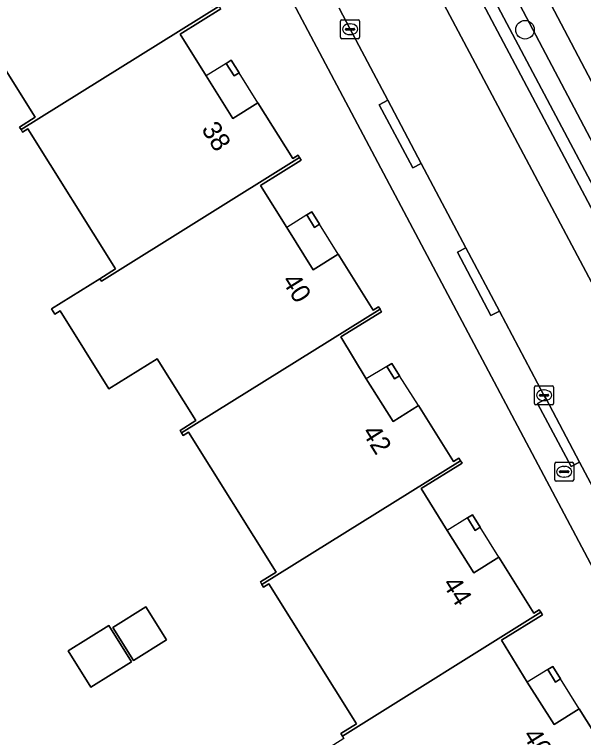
# Model space of a CAD drawing. Extents: x 158835 to 160077, y 386387 to 387778.
# Drawn here: x 159225.67 to 159255.61, y 387026.31 to 387064.34 of the extents above; entities that cross this region are included whole.
import ezdxf

# ---------------------------------------------------------------- set-up
doc = ezdxf.new("R2010")
doc.units = 0
for name, color, linetype in [('IMGEO_Berm_groen', 7, 'Continuous'), ('IMGEO_Boom', 7, 'Continuous'), ('IMGEO_Brandkraan', 7, 'Continuous'), ('IMGEO_Erf', 7, 'Continuous'), ('IMGEO_Kolk', 7, 'Continuous'), ('IMGEO_Oever', 7, 'Continuous'), ('IMGEO_Pand', 7, 'Continuous'), ('IMGEO_Pand_nummerreeks', 7, 'Continuous'), ('IMGEO_Pand_overbouw', 7, 'Continuous'), ('IMGEO_Parkeervlak_open', 7, 'Continuous'), ('IMGEO_Rijbaan_lokaal_open', 7, 'Continuous'), ('IMGEO_Voetpad_open', 7, 'Continuous'), ('IMGEO_Waterloop', 7, 'Continuous')]:
    doc.layers.add(name, color=color, linetype=linetype)

msp = doc.modelspace()

# ---------------------------------------------------------------- linework, layer by layer
at = {"layer": 'IMGEO_Berm_groen'}
for points in [[(159232.161, 387115.069), (159226.137, 387111.804), (159270.438, 387028.309), (159271.271, 387028.784), (159272.996, 387034.162)], [(159268.044, 387034.942), (159228.447, 387109.997)]]:
    msp.add_lwpolyline(points, dxfattribs=at)
at = {"layer": 'IMGEO_Boom'}
msp.add_circle((159252.526, 387063.537), 0.489, dxfattribs=at)
at = {"layer": 'IMGEO_Brandkraan'}
for p, q in [((159254.089, 387039.861), (159254.089, 387040.713)), ((159254.164, 387040.787), (159255.016, 387040.787)), ((159255.09, 387040.713), (159255.09, 387039.861)), ((159254.348, 387040.281), (159254.348, 387040.293)), ((159254.786, 387040.244), (159254.388, 387040.244)), ((159254.391, 387040.33), (159254.789, 387040.33)), ((159254.577, 387040.567), (159254.602, 387040.567)), ((159254.832, 387040.293), (159254.832, 387040.281)), ((159254.6, 387040.007), (159254.575, 387040.007)), ((159255.016, 387039.787), (159254.164, 387039.787))]:
    msp.add_line(p, q, dxfattribs=at)
for points in [[(159254.089, 387039.861), (159254.089, 387040.713)], [(159254.164, 387040.787), (159255.016, 387040.787)], [(159255.09, 387040.713), (159255.09, 387039.861)], [(159255.016, 387039.787), (159254.164, 387039.787)]]:
    msp.add_lwpolyline(points, dxfattribs=at)
for centre, radius, start, end in [((159254.166, 387040.711), 0.0765, 91.552, 178.448), ((159254.166, 387040.711), 0.0765, 91.552, 178.448), ((159255.014, 387040.711), 0.0765, 1.552, 88.448), ((159255.014, 387040.711), 0.0765, 1.552, 88.448), ((159254.388, 387040.29), 0.0403, 85.8775, 175.7526), ((159254.385, 387040.28), 0.0366, 178.938, 274.7102), ((159254.789, 387040.287), 0.043, 264.8664, 352.4533), ((159254.793, 387040.292), 0.0386, 1.7309, 96.639), ((159254.166, 387039.863), 0.0765, 181.552, 268.448), ((159254.166, 387039.863), 0.0765, 181.552, 268.448), ((159255.014, 387039.863), 0.0765, 271.552, 358.448), ((159255.014, 387039.863), 0.0765, 271.552, 358.448)]:
    msp.add_arc(centre, radius, start, end, dxfattribs=at)
for centre, major_axis, ratio, start_param, end_param in [((159254.576, 387040.287), (-0.387, 0.002), 0.722429, 4.712389, 7.853982), ((159254.601, 387040.287), (-0.39, 0.002), 0.717154, 1.570796, 4.712389)]:
    msp.add_ellipse(centre, major_axis=major_axis, ratio=ratio, start_param=start_param, end_param=end_param, dxfattribs=at)
at = {"layer": 'IMGEO_Erf'}
for points in [[(159261.184, 387025.643), (159192.812, 387154.528)], [(159243.003, 387026.25), (159242.922, 387026.379), (159242.837, 387026.515), (159243.66, 387027.029), (159239.055, 387034.398), (159238.776, 387034.223), (159238.691, 387034.359), (159238.606, 387034.495), (159239.429, 387035.009), (159234.83, 387042.369), (159234.55, 387042.195), (159234.465, 387042.33), (159234.38, 387042.466), (159235.211, 387042.985), (159233.182, 387046.233), (159230.638, 387044.643), (159228.068, 387048.756), (159227.788, 387048.581), (159227.619, 387048.853), (159230.162, 387050.442), (159230.985, 387050.956), (159226.381, 387058.325), (159226.101, 387058.15), (159226.016, 387058.286), (159225.932, 387058.422), (159226.754, 387058.936), (159222.155, 387066.296)], [(159236.531, 387064.64), (159234.39, 387063.311), (159235.756, 387061.11), (159237.152, 387058.876), (159238.473, 387059.701), (159240.308, 387056.773), (159240.588, 387056.948), (159240.673, 387056.813), (159240.758, 387056.677), (159238.613, 387055.337), (159239.99, 387053.137), (159241.386, 387050.903), (159242.706, 387051.728), (159244.538, 387048.796), (159244.818, 387048.97), (159244.903, 387048.834), (159244.987, 387048.699), (159242.834, 387047.389), (159244.18, 387045.177), (159245.598, 387042.94), (159246.918, 387043.765), (159248.767, 387040.829), (159249.047, 387041.006), (159249.133, 387040.87), (159249.218, 387040.734), (159247.073, 387039.403), (159248.44, 387037.198), (159249.837, 387034.964), (159251.158, 387035.789), (159252.992, 387032.856), (159253.272, 387033.032), (159253.357, 387032.896), (159253.442, 387032.76), (159251.286, 387031.433), (159252.65, 387029.217), (159254.063, 387026.986), (159255.383, 387027.811), (159257.214, 387024.885)]]:
    msp.add_lwpolyline(points, dxfattribs=at)
for points in [[(159237.076, 387061.93), (159237.485, 387061.278), (159237.222, 387061.113), (159236.813, 387061.766)], [(159241.313, 387053.959), (159241.721, 387053.306), (159241.458, 387053.142), (159241.05, 387053.795)], [(159245.516, 387045.99), (159245.927, 387045.338), (159245.664, 387045.173), (159245.251, 387045.829)], [(159249.763, 387038.019), (159250.171, 387037.366), (159249.908, 387037.202), (159249.5, 387037.856)], [(159233.67, 387031.446), (159231.931, 387030.359), (159230.843, 387032.098), (159232.582, 387033.185)], [(159231.831, 387030.293), (159229.688, 387028.952), (159228.493, 387030.863), (159230.637, 387032.203)], [(159253.988, 387030.041), (159254.396, 387029.388), (159254.134, 387029.224), (159253.724, 387029.878)]]:
    msp.add_lwpolyline(points, close=True, dxfattribs=at)
at = {"layer": 'IMGEO_Kolk'}
for p, q in [((159242.824, 387063.139), (159242.824, 387063.991)), ((159242.899, 387064.065), (159243.751, 387064.065)), ((159243.312, 387063.845), (159243.337, 387063.845)), ((159243.825, 387063.991), (159243.825, 387063.139)), ((159243.083, 387063.559), (159243.083, 387063.571)), ((159243.521, 387063.522), (159243.123, 387063.522)), ((159243.126, 387063.608), (159243.524, 387063.608)), ((159243.567, 387063.571), (159243.567, 387063.559)), ((159243.751, 387063.065), (159242.899, 387063.065)), ((159243.335, 387063.285), (159243.31, 387063.285)), ((159253.104, 387044.812), (159253.956, 387044.812)), ((159253.029, 387043.886), (159253.029, 387044.738)), ((159253.517, 387044.592), (159253.542, 387044.592)), ((159254.03, 387044.738), (159254.03, 387043.886)), ((159253.288, 387044.306), (159253.288, 387044.318)), ((159253.726, 387044.269), (159253.328, 387044.269)), ((159253.331, 387044.355), (159253.729, 387044.355)), ((159253.772, 387044.318), (159253.772, 387044.306)), ((159253.956, 387043.812), (159253.104, 387043.812)), ((159253.54, 387044.032), (159253.515, 387044.032))]:
    msp.add_line(p, q, dxfattribs=at)
for points in [[(159242.824, 387063.139), (159242.824, 387063.991)], [(159242.899, 387064.065), (159243.751, 387064.065)], [(159243.825, 387063.991), (159243.825, 387063.139)], [(159243.751, 387063.065), (159242.899, 387063.065)], [(159253.104, 387044.812), (159253.956, 387044.812)], [(159253.029, 387043.886), (159253.029, 387044.738)], [(159254.03, 387044.738), (159254.03, 387043.886)], [(159253.956, 387043.812), (159253.104, 387043.812)]]:
    msp.add_lwpolyline(points, dxfattribs=at)
for centre, radius, start, end in [((159242.901, 387063.989), 0.0765, 91.552, 178.448), ((159242.901, 387063.989), 0.0765, 91.552, 178.448), ((159243.749, 387063.989), 0.0765, 1.552, 88.448), ((159243.749, 387063.989), 0.0765, 1.552, 88.448), ((159243.123, 387063.568), 0.0403, 85.8775, 175.7526), ((159243.12, 387063.558), 0.0366, 178.938, 274.7102), ((159243.524, 387063.565), 0.043, 264.8664, 352.4533), ((159243.528, 387063.57), 0.0386, 1.7309, 96.639), ((159242.901, 387063.141), 0.0765, 181.552, 268.448), ((159242.901, 387063.141), 0.0765, 181.552, 268.448), ((159243.749, 387063.141), 0.0765, 271.552, 358.448), ((159243.749, 387063.141), 0.0765, 271.552, 358.448), ((159253.106, 387044.736), 0.0765, 91.552, 178.448), ((159253.106, 387044.736), 0.0765, 91.552, 178.448), ((159253.954, 387044.736), 0.0765, 1.552, 88.448), ((159253.954, 387044.736), 0.0765, 1.552, 88.448), ((159253.328, 387044.315), 0.0403, 85.8775, 175.7526), ((159253.325, 387044.305), 0.0366, 178.938, 274.7102), ((159253.729, 387044.312), 0.043, 264.8664, 352.4533), ((159253.733, 387044.317), 0.0386, 1.7309, 96.639), ((159253.106, 387043.888), 0.0765, 181.552, 268.448), ((159253.106, 387043.888), 0.0765, 181.552, 268.448), ((159253.954, 387043.888), 0.0765, 271.552, 358.448), ((159253.954, 387043.888), 0.0765, 271.552, 358.448)]:
    msp.add_arc(centre, radius, start, end, dxfattribs=at)
for centre, major_axis, ratio, start_param, end_param in [((159243.311, 387063.565), (-0.387, 0.002), 0.722429, 4.712389, 7.853982), ((159243.336, 387063.565), (-0.39, 0.002), 0.717154, 1.570796, 4.712389), ((159253.516, 387044.312), (-0.387, 0.002), 0.722429, 4.712389, 7.853982), ((159253.541, 387044.312), (-0.39, 0.002), 0.717154, 1.570796, 4.712389)]:
    msp.add_ellipse(centre, major_axis=major_axis, ratio=ratio, start_param=start_param, end_param=end_param, dxfattribs=at)
at = {"layer": 'IMGEO_Oever'}
for points in [[(159228.447, 387109.997), (159268.044, 387034.942)], [(159232.07, 387109.817), (159271.865, 387035.443), (159269.914, 387034.437), (159263.508, 387046.573), (159249.976, 387072.343), (159230.366, 387108.873)]]:
    msp.add_lwpolyline(points, dxfattribs=at)
at = {"layer": 'IMGEO_Pand'}
for points in [[(159234.24, 387067.673), (159232.92, 387066.848), (159231.509, 387069.082), (159230.151, 387071.292), (159232.302, 387072.614), (159232.217, 387072.75), (159221.79, 387066.257), (159221.875, 387066.121), (159222.155, 387066.296), (159226.754, 387058.936), (159225.932, 387058.422), (159226.016, 387058.286), (159236.446, 387064.776), (159236.361, 387064.912), (159236.08, 387064.736)], [(159238.473, 387059.701), (159237.152, 387058.876), (159235.756, 387061.11), (159234.39, 387063.311), (159236.531, 387064.64), (159236.446, 387064.776), (159226.016, 387058.286), (159226.101, 387058.15), (159226.381, 387058.325), (159230.985, 387050.956), (159230.162, 387050.442), (159230.247, 387050.306), (159240.673, 387056.813), (159240.588, 387056.948), (159240.308, 387056.773)], [(159237.076, 387061.93), (159236.813, 387061.766), (159237.222, 387061.113), (159237.485, 387061.278)], [(159242.706, 387051.728), (159241.386, 387050.903), (159239.99, 387053.137), (159238.613, 387055.337), (159240.758, 387056.677), (159240.673, 387056.813), (159230.247, 387050.306), (159230.162, 387050.442), (159227.619, 387048.853), (159227.788, 387048.581), (159228.068, 387048.756), (159230.638, 387044.643), (159233.182, 387046.233), (159235.211, 387042.985), (159234.38, 387042.466), (159234.465, 387042.33), (159244.903, 387048.834), (159244.818, 387048.97), (159244.538, 387048.796)], [(159241.313, 387053.959), (159241.05, 387053.795), (159241.458, 387053.142), (159241.721, 387053.306)], [(159246.918, 387043.765), (159245.598, 387042.94), (159244.18, 387045.177), (159242.834, 387047.389), (159244.987, 387048.699), (159244.903, 387048.834), (159234.465, 387042.33), (159234.55, 387042.195), (159234.83, 387042.369), (159239.429, 387035.009), (159238.606, 387034.495), (159238.691, 387034.359), (159249.133, 387040.87), (159249.047, 387041.006), (159248.767, 387040.829)], [(159245.516, 387045.99), (159245.251, 387045.829), (159245.664, 387045.173), (159245.927, 387045.338)], [(159251.158, 387035.789), (159249.837, 387034.964), (159248.44, 387037.198), (159247.073, 387039.403), (159249.218, 387040.734), (159249.133, 387040.87), (159238.691, 387034.359), (159238.776, 387034.223), (159239.055, 387034.398), (159243.66, 387027.029), (159242.837, 387026.515), (159242.922, 387026.379), (159253.357, 387032.896), (159253.272, 387033.032), (159252.992, 387032.856)], [(159249.763, 387038.019), (159249.5, 387037.856), (159249.908, 387037.202), (159250.171, 387037.366)], [(159230.843, 387032.098), (159231.931, 387030.359), (159233.67, 387031.446), (159232.582, 387033.185)], [(159257.664, 387024.789), (159257.494, 387025.06), (159257.214, 387024.885), (159255.383, 387027.811), (159254.063, 387026.986), (159252.65, 387029.217), (159251.286, 387031.433), (159253.442, 387032.76), (159253.357, 387032.896), (159242.922, 387026.379), (159243.003, 387026.25), (159240.22, 387024.511), (159244.789, 387017.2), (159247.571, 387018.938), (159249.1, 387016.492), (159253.864, 387019.466), (159253.695, 387019.738), (159253.363, 387019.532), (159252.205, 387021.394)], [(159228.493, 387030.863), (159229.688, 387028.952), (159231.831, 387030.293), (159230.637, 387032.203)], [(159253.988, 387030.041), (159253.724, 387029.878), (159254.134, 387029.224), (159254.396, 387029.388)]]:
    msp.add_lwpolyline(points, close=True, dxfattribs=at)
at = {"layer": 'IMGEO_Pand_overbouw'}
for points in [[(159237.485, 387061.278), (159237.076, 387061.93), (159236.813, 387061.766), (159235.756, 387061.11), (159237.152, 387058.876), (159238.473, 387059.701)], [(159241.721, 387053.306), (159241.313, 387053.959), (159241.05, 387053.795), (159239.99, 387053.137), (159241.386, 387050.903), (159242.706, 387051.728)], [(159245.927, 387045.338), (159245.516, 387045.99), (159245.251, 387045.829), (159244.18, 387045.177), (159245.598, 387042.94), (159246.918, 387043.765)], [(159250.171, 387037.366), (159249.763, 387038.019), (159249.5, 387037.856), (159248.44, 387037.198), (159249.837, 387034.964), (159251.158, 387035.789)], [(159254.396, 387029.388), (159253.988, 387030.041), (159253.724, 387029.878), (159252.65, 387029.217), (159254.063, 387026.986), (159255.383, 387027.811)]]:
    msp.add_lwpolyline(points, close=True, dxfattribs=at)
at = {"layer": 'IMGEO_Parkeervlak_open'}
msp.add_lwpolyline([(159248.115, 387065.172), (159257.979, 387046.591), (159267.363, 387028.878), (159268.082, 387027.672), (159268.061, 387027.769), (159268.036, 387027.936), (159268.027, 387028.103), (159268.033, 387028.272), (159268.053, 387028.439), (159268.089, 387028.603), (159268.468, 387030.087), (159268.49, 387030.166), (159268.504, 387030.247), (159268.512, 387030.329), (159268.512, 387030.411), (159268.504, 387030.493), (159268.49, 387030.574), (159268.468, 387030.653), (159268.439, 387030.73), (159268.404, 387030.804), (159268.384, 387030.839), (159217.085, 387127.542)], dxfattribs=at)
at = {"layer": 'IMGEO_Rijbaan_lokaal_open'}
msp.add_lwpolyline([(159242.753, 387064.674), (159243.322, 387063.566), (159245.304, 387059.827), (159247.064, 387056.499), (159249.413, 387052.073), (159251.18, 387048.74), (159253.527, 387044.313), (159253.634, 387044.117), (159255.396, 387040.792), (159257.738, 387036.381), (159259.501, 387033.04), (159262.771, 387026.855), (159263.643, 387025.149), (159268.082, 387027.672), (159267.363, 387028.878), (159257.979, 387046.591), (159248.115, 387065.172)], dxfattribs=at)
at = {"layer": 'IMGEO_Voetpad_open'}
for points in [[(159192.812, 387154.528), (159261.184, 387025.643)], [(159217.085, 387127.542), (159268.384, 387030.839), (159268.404, 387030.804), (159268.439, 387030.73), (159268.468, 387030.653), (159268.49, 387030.574), (159268.504, 387030.493), (159268.512, 387030.411), (159268.512, 387030.329), (159268.504, 387030.247), (159268.49, 387030.166), (159268.468, 387030.087), (159268.089, 387028.603), (159268.053, 387028.439), (159268.033, 387028.272), (159268.027, 387028.103), (159268.036, 387027.936), (159268.061, 387027.769), (159268.082, 387027.672), (159268.126, 387027.544), (159268.184, 387027.373), (159268.337, 387027.091), (159270.438, 387028.309), (159226.137, 387111.804)], [(159263.643, 387025.149), (159262.771, 387026.855), (159259.501, 387033.04), (159259.059, 387032.807), (159257.296, 387036.148), (159257.738, 387036.381), (159255.396, 387040.792), (159254.955, 387040.558), (159253.193, 387043.883), (159253.634, 387044.117), (159253.527, 387044.313), (159251.18, 387048.74), (159250.738, 387048.506), (159248.972, 387051.839), (159249.413, 387052.073), (159247.064, 387056.499), (159246.623, 387056.266), (159244.863, 387059.594), (159245.304, 387059.827), (159243.322, 387063.566), (159242.753, 387064.674)]]:
    msp.add_lwpolyline(points, dxfattribs=at)
for points in [[(159245.304, 387059.827), (159244.863, 387059.594), (159246.623, 387056.266), (159247.064, 387056.499)], [(159251.18, 387048.74), (159249.413, 387052.073), (159248.972, 387051.839), (159250.738, 387048.506)], [(159255.396, 387040.792), (159253.634, 387044.117), (159253.193, 387043.883), (159254.955, 387040.558)]]:
    msp.add_lwpolyline(points, close=True, dxfattribs=at)
at = {"layer": 'IMGEO_Waterloop'}
msp.add_lwpolyline([(159230.366, 387108.873), (159249.976, 387072.343), (159263.508, 387046.573), (159269.914, 387034.437), (159271.865, 387035.443), (159232.07, 387109.817)], dxfattribs=at)

# ---------------------------------------------------------------- texts
at = {"layer": 'IMGEO_Pand_nummerreeks'}
for s, rotation, p in [('38', 302.074, (159235.476, 387058.308)), ('40', 301.988, (159239.708, 387050.338)), ('42', 302.2057, (159243.925, 387042.363)), ('44', 302.0224, (159248.159, 387034.399)), ('46', 302.0339, (159252.383, 387026.424))]:
    msp.add_text(s, height=1, rotation=rotation, dxfattribs=at).set_placement(p)

doc.saveas('drawing.dxf')
